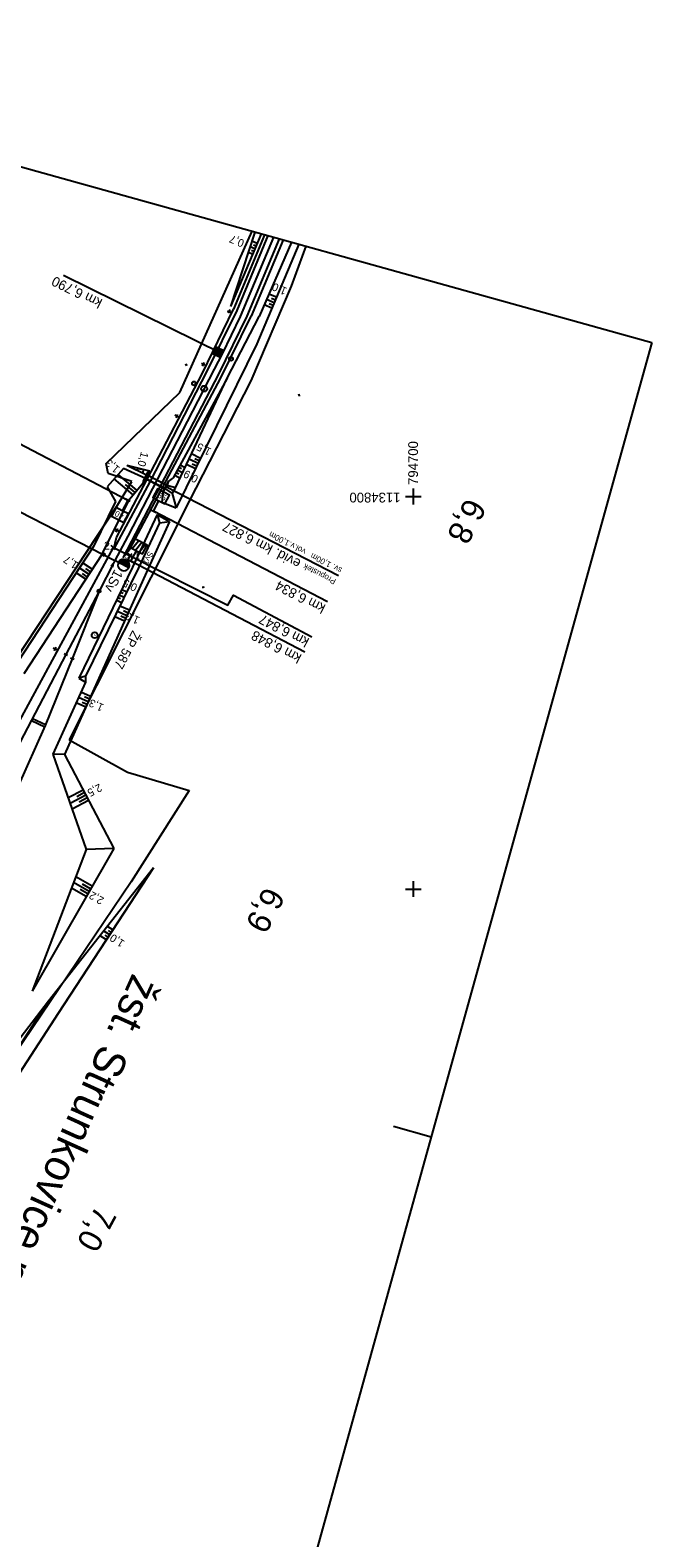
# Model space of a CAD drawing. Extents: x -795094 to -794639, y -1135368 to -1134681.
# Drawn here: x -794797.7 to -794639.2, y -1135065.2 to -1134681.2 of the extents above; entities that cross this region are included whole.
import ezdxf

# ---------------------------------------------------------------- set-up
doc = ezdxf.new("R2010")
doc.units = 0
for name, color, linetype in [('0381KM005-009P - Vrstva 1', 7, 'Continuous'), ('0381KM005-009P - Vrstva 19', 7, 'Continuous'), ('0381KM005-009P - Vrstva 2', 7, 'Continuous'), ('0381KM005-009P - Vrstva 23', 7, 'Continuous'), ('0381KM005-009P - Vrstva 28', 7, 'Continuous'), ('0381KM005-009P - Vrstva 3', 7, 'Continuous'), ('0381KM005-009P - Vrstva 33', 7, 'Continuous'), ('0381KM005-009P - Vrstva 4', 7, 'Continuous'), ('0381KM005-009P - Vrstva 48', 7, 'Continuous'), ('0381KM005-009P - Vrstva 49', 7, 'Continuous'), ('0381KM005-009P - Vrstva 5', 7, 'Continuous'), ('0381KM005-009P - Vrstva 51', 7, 'Continuous'), ('0381KM005-009P - Vrstva 6', 7, 'Continuous'), ('0381KM005-009P - Vrstva 7', 7, 'Continuous'), ('Default', 7, 'Continuous'), ('formát', 7, 'Continuous'), ('hran DP - hran DP', 7, 'Continuous'), ('krizky_1000 - souradnice', 7, 'Continuous'), ('krizky_1000 - Vrstva 1', 7, 'Continuous'), ('PSR_C2_1_Lomove_body_Strunkovice - Vrstva 60', 7, 'Continuous'), ('PSR_C2_1_trasa_Strunkovice - Kabelová trasa', 7, 'Continuous'), ('vyt_sit - stávající', 7, 'Continuous')]:
    doc.layers.add(name, color=color, linetype=linetype)

msp = doc.modelspace()

# ---------------------------------------------------------------- linework, layer by layer
at = {"layer": '0381KM005-009P - Vrstva 1'}
for points in [[(-794735.66, -1134733.94), (-794744.1, -1134754.13), (-794748.76, -1134763.69), (-794750.73, -1134767.6), (-794757.62, -1134780.92)], [(-794757.62, -1134780.92), (-794772.8, -1134810.07), (-794776.07, -1134816.32)], [(-794776.07, -1134816.32), (-794776.43, -1134817.02), (-794780.11, -1134824.07), (-794788.58, -1134840.28)], [(-794776.07, -1134816.32), (-794776.43, -1134817.02), (-794780.11, -1134824.07), (-794786.96, -1134841.36)], [(-794788.58, -1134840.28), (-794803.19, -1134868.16), (-794810.38, -1134881.86), (-794818.66, -1134897.6), (-794826.62, -1134912.5), (-794834.33, -1134926.85), (-794861.92, -1134977.99)], [(-794786.96, -1134841.36), (-794793.84, -1134858.32), (-794800.91, -1134874.12), (-794807.73, -1134887.87), (-794826.52, -1134924.29), (-794833.34, -1134937.13), (-794839.37, -1134947.86), (-794840.75, -1134950.16), (-794846.08, -1134958.61), (-794850.88, -1134965.55), (-794860.1, -1134978.74)]]:
    msp.add_lwpolyline(points, dxfattribs=at)
at = {"layer": '0381KM005-009P - Vrstva 19'}
for p, q in [((-794767.26, -1134793.5), (-794768.87, -1134796.52)), ((-794768.87, -1134796.52), (-794768.27, -1134795.41)), ((-794768.27, -1134795.41), (-794767.82, -1134794.57)), ((-794768.27, -1134795.41), (-794768.27, -1134795.41)), ((-794763.3, -1134797.99), (-794768.27, -1134795.41)), ((-794768.27, -1134795.41), (-794763.33, -1134798.06)), ((-794767.82, -1134794.57), (-794767.26, -1134793.5)), ((-794767.82, -1134794.57), (-794767.82, -1134794.57)), ((-794762.85, -1134797.19), (-794767.82, -1134794.57)), ((-794762.89, -1134797.15), (-794767.82, -1134794.57)), ((-794763.85, -1134798.98), (-794762.37, -1134796.11)), ((-794762.89, -1134797.15), (-794763.33, -1134798.06)), ((-794762.85, -1134797.19), (-794762.89, -1134797.15)), ((-794762.37, -1134796.11), (-794762.85, -1134797.19)), ((-794763.3, -1134797.99), (-794763.85, -1134798.98)), ((-794763.33, -1134798.06), (-794763.3, -1134797.99)), ((-794719.1, -1134820.2), (-794763.06, -1134797.51))]:
    msp.add_line(p, q, dxfattribs=at)
at = {"layer": '0381KM005-009P - Vrstva 2'}
for p, q in [((-794815.95, -1134795.81), (-794776.07, -1134816.32)), ((-794775.14, -1134816.79), (-794776.07, -1134816.32)), ((-794774.93, -1134816.49), (-794774.77, -1134816.98)), ((-794774.61, -1134816.22), (-794774.29, -1134817.23)), ((-794774.26, -1134816.06), (-794773.81, -1134817.48)), ((-794773.89, -1134816), (-794773.33, -1134817.72)), ((-794773.47, -1134816.05), (-794772.86, -1134817.97)), ((-794773, -1134816.26), (-794772.46, -1134817.95)), ((-794772.54, -1134818.13), (-794775.14, -1134816.79)), ((-794772.54, -1134818.13), (-794772.54, -1134818.13)), ((-794780.11, -1134824.07), (-794786.96, -1134841.36)), ((-794788.14, -1134840.51), (-794789.03, -1134840.05)), ((-794786.49, -1134841.55), (-794787.42, -1134841.18))]:
    msp.add_line(p, q, dxfattribs=at)
for points in [[(-794776.07, -1134816.32), (-794776.43, -1134817.02), (-794780.11, -1134824.07), (-794788.58, -1134840.28)], [(-794776.64, -1134817.99), (-794776.43, -1134817.02), (-794777.1, -1134817.76)]]:
    msp.add_lwpolyline(points, dxfattribs=at)
msp.add_circle((-794780.11, -1134824.07), 0.4, dxfattribs=at)
for start, end in [(332.7997, 152.7606), (152.7102, 333.1797)]:
    msp.add_arc((-794773.84, -1134817.46), 1.46, start, end, dxfattribs=at)
at = {"layer": '0381KM005-009P - Vrstva 28'}
msp.add_line((-794746.44, -1134764.88), (-794746.48, -1134764.97), dxfattribs=at)
msp.add_circle((-794746.46, -1134764.93), 0.5, dxfattribs=at)
at = {"layer": '0381KM005-009P - Vrstva 3'}
for p, q in [((-794748.76, -1134763.69), (-794789.21, -1134743.71)), ((-794750.35, -1134762.39), (-794749.67, -1134764.36)), ((-794750.12, -1134761.92), (-794749.2, -1134764.59)), ((-794749.64, -1134762.15), (-794748.96, -1134764.11)), ((-794749.16, -1134762.38), (-794748.73, -1134763.64)), ((-794748.69, -1134762.61), (-794748.5, -1134763.16)), ((-794750.81, -1134763.35), (-794750.63, -1134763.89)), ((-794750.58, -1134762.87), (-794750.15, -1134764.12))]:
    msp.add_line(p, q, dxfattribs=at)
msp.add_lwpolyline([(-794748.32, -1134762.79), (-794749.2, -1134764.59), (-794750.99, -1134763.71), (-794750.12, -1134761.92)], close=True, dxfattribs=at)
at = {"layer": '0381KM005-009P - Vrstva 33'}
msp.add_line((-794768.83, -1134796.2), (-794767.55, -1134793.7), dxfattribs=at)
at = {"layer": '0381KM005-009P - Vrstva 4'}
for points in [[(-794737.95, -1134733.31), (-794745.79, -1134752.29)], [(-794737.06, -1134733.55), (-794744.97, -1134752.65)], [(-794734.21, -1134734.35), (-794742.45, -1134754.09)], [(-794733.14, -1134734.64), (-794741.33, -1134754.03)], [(-794744.97, -1134752.65), (-794752.57, -1134767.89), (-794767.17, -1134796.25), (-794776.32, -1134813.35), (-794775.69, -1134810.46), (-794767.89, -1134795.76), (-794753.75, -1134768.59), (-794745.79, -1134752.29)], [(-794742.45, -1134754.09), (-794749.67, -1134768.83), (-794764.43, -1134797.23), (-794773.98, -1134815.47), (-794772.27, -1134813.39), (-794763.8, -1134797.42), (-794749.03, -1134769.75), (-794741.33, -1134754.03)]]:
    msp.add_lwpolyline(points, dxfattribs=at)
at = {"layer": '0381KM005-009P - Vrstva 48'}
for p, q in [((-794739.8, -1134735.54), (-794741.14, -1134734.97)), ((-794740.97, -1134738.3), (-794742.08, -1134737.83)), ((-794740.39, -1134736.92), (-794741.61, -1134736.4)), ((-794740.68, -1134737.61), (-794741.26, -1134737.36)), ((-794740.09, -1134736.23), (-794740.73, -1134735.96)), ((-794736.03, -1134752.03), (-794738.01, -1134751.2)), ((-794735.45, -1134750.65), (-794737.41, -1134749.82)), ((-794734.87, -1134749.26), (-794736.81, -1134748.45)), ((-794735.74, -1134751.34), (-794736.72, -1134750.92)), ((-794735.16, -1134749.96), (-794736.13, -1134749.54)), ((-794754.22, -1134790.28), (-794756.53, -1134789.14)), ((-794770.26, -1134792.73), (-794770.4, -1134793.3)), ((-794769.53, -1134792.91), (-794769.62, -1134793.27)), ((-794768.8, -1134793.1), (-794769.03, -1134793.97)), ((-794760.11, -1134793.21), (-794758.79, -1134793.93)), ((-794759.75, -1134792.55), (-794759.11, -1134792.9)), ((-794759.39, -1134791.89), (-794758.15, -1134792.57)), ((-794755.55, -1134792.97), (-794757.81, -1134791.86)), ((-794754.88, -1134791.63), (-794757.17, -1134790.5)), ((-794755.21, -1134792.3), (-794756.35, -1134791.74)), ((-794754.55, -1134790.95), (-794755.7, -1134790.39)), ((-794771.4, -1134799.56), (-794776.25, -1134795.52)), ((-794770.44, -1134798.41), (-794775.25, -1134794.4)), ((-794770.92, -1134798.98), (-794773.33, -1134796.97)), ((-794760.82, -1134794.53), (-794759.43, -1134795.29)), ((-794760.46, -1134793.87), (-794759.79, -1134794.24)), ((-794783.51, -1134821.05), (-794785.98, -1134819.43)), ((-794782.69, -1134819.79), (-794785.16, -1134818.18)), ((-794783.1, -1134820.42), (-794784.34, -1134819.61)), ((-794781.87, -1134818.54), (-794784.33, -1134816.93)), ((-794782.28, -1134819.17), (-794783.51, -1134818.36)), ((-794774.33, -1134823.66), (-794773.01, -1134824.29)), ((-794775.63, -1134826.36), (-794774.33, -1134826.99)), ((-794775.3, -1134825.69), (-794774.65, -1134826)), ((-794774.98, -1134825.01), (-794773.67, -1134825.64)), ((-794772.39, -1134828.99), (-794774.79, -1134827.92)), ((-794774.65, -1134824.34), (-794774, -1134824.65)), ((-794773.62, -1134831.73), (-794776.11, -1134830.61)), ((-794773.01, -1134830.36), (-794775.45, -1134829.27)), ((-794773.32, -1134831.05), (-794774.55, -1134830.49)), ((-794772.7, -1134829.68), (-794773.91, -1134829.14)), ((-794782.26, -1134850.93), (-794784.73, -1134849.82)), ((-794782.56, -1134851.61), (-794783.8, -1134851.06)), ((-794783.49, -1134853.67), (-794785.97, -1134852.55)), ((-794782.87, -1134852.3), (-794785.35, -1134851.19)), ((-794783.18, -1134852.98), (-794784.42, -1134852.43)), ((-794784.18, -1134874.77), (-794788, -1134876.78)), ((-794783.48, -1134876.09), (-794787.5, -1134878.21)), ((-794782.78, -1134877.42), (-794787, -1134879.64)), ((-794783.83, -1134875.43), (-794785.79, -1134876.46)), ((-794783.13, -1134876.76), (-794785.19, -1134877.84)), ((-794781.89, -1134899.28), (-794786.07, -1134896.89)), ((-794783.38, -1134901.88), (-794787.15, -1134899.73)), ((-794782.63, -1134900.58), (-794786.61, -1134898.31)), ((-794783, -1134901.23), (-794784.94, -1134900.12)), ((-794782.26, -1134899.93), (-794784.3, -1134898.76)), ((-794778.21, -1134912.91), (-794779.82, -1134911.86)), ((-794777.39, -1134911.65), (-794778.88, -1134910.67)), ((-794777.8, -1134912.28), (-794778.58, -1134911.77)), ((-794776.57, -1134910.4), (-794777.95, -1134909.49)), ((-794776.98, -1134911.03), (-794777.7, -1134910.55))]:
    msp.add_line(p, q, dxfattribs=at)
at = {"layer": '0381KM005-009P - Vrstva 49'}
for p, q in [((-794740.37, -1134732.63), (-794746.6, -1134751.57)), ((-794738.76, -1134733.08), (-794746.6, -1134751.57)), ((-794729.18, -1134735.74), (-794739.85, -1134761.11)), ((-794731.07, -1134735.22), (-794739.3, -1134754.18)), ((-794747.45, -1134769.82), (-794739.3, -1134754.18)), ((-794739.85, -1134761.11), (-794760.44, -1134802.9)), ((-794757.66, -1134766.37), (-794758.14, -1134766.52)), ((-794757.97, -1134766.21), (-794757.82, -1134766.69)), ((-794747.45, -1134769.82), (-794761.22, -1134795.28)), ((-794760.61, -1134797.81), (-794747.45, -1134769.82)), ((-794728.89, -1134774.12), (-794729.36, -1134774.28)), ((-794729.21, -1134773.96), (-794729.05, -1134774.44)), ((-794773.87, -1134792.87), (-794778.08, -1134797.54)), ((-794768.27, -1134795.41), (-794773.87, -1134792.87)), ((-794773.02, -1134792.01), (-794767.82, -1134794.57)), ((-794773.02, -1134792.01), (-794767.26, -1134793.5)), ((-794772.33, -1134800.68), (-794768.87, -1134796.52)), ((-794768.27, -1134795.41), (-794768.87, -1134796.52)), ((-794767.82, -1134794.57), (-794767.26, -1134793.5)), ((-794762.37, -1134796.11), (-794763.85, -1134798.98)), ((-794762.85, -1134797.19), (-794762.37, -1134796.11)), ((-794760.61, -1134797.81), (-794762.85, -1134797.19)), ((-794761.22, -1134795.28), (-794762.37, -1134796.11)), ((-794779.34, -1134814.68), (-794772.33, -1134800.68)), ((-794778.08, -1134797.54), (-794775.92, -1134801.3)), ((-794763.85, -1134798.98), (-794764.14, -1134801.43)), ((-794763.3, -1134797.99), (-794763.85, -1134798.98)), ((-794763.3, -1134797.99), (-794761.44, -1134799.24)), ((-794761.44, -1134799.24), (-794760.61, -1134797.81)), ((-794761.44, -1134799.24), (-794760.44, -1134802.9)), ((-794775.92, -1134801.3), (-794781.56, -1134812.71)), ((-794765.33, -1134804.62), (-794771.57, -1134817.97)), ((-794765.33, -1134804.62), (-794764.66, -1134806.73)), ((-794765.33, -1134804.62), (-794762.15, -1134806.37)), ((-794764.14, -1134801.43), (-794760.44, -1134802.9)), ((-794764.66, -1134806.73), (-794770.02, -1134818.19)), ((-794762.15, -1134806.37), (-794768.04, -1134819.3)), ((-794764.66, -1134806.73), (-794762.15, -1134806.37)), ((-794781.56, -1134812.71), (-794806.26, -1134850.22)), ((-794779.34, -1134814.68), (-794799.26, -1134845.15)), ((-794768.04, -1134819.3), (-794788.91, -1134865.74)), ((-794771.57, -1134817.97), (-794785.26, -1134846.3)), ((-794770.02, -1134818.19), (-794783.54, -1134845.78)), ((-794753.32, -1134823.06), (-794753.8, -1134823.21)), ((-794753.64, -1134822.9), (-794753.49, -1134823.38)), ((-794783.54, -1134845.78), (-794785.26, -1134846.3)), ((-794785.26, -1134846.3), (-794783.58, -1134847.29)), ((-794783.54, -1134845.78), (-794783.58, -1134847.29)), ((-794783.58, -1134847.29), (-794791.9, -1134865.62)), ((-794791.9, -1134865.62), (-794783.41, -1134889.91)), ((-794788.91, -1134865.74), (-794791.9, -1134865.62)), ((-794788.91, -1134865.74), (-794776.38, -1134889.62)), ((-794776.38, -1134889.62), (-794797.15, -1134926.02)), ((-794783.41, -1134889.91), (-794797.15, -1134926.02)), ((-794776.38, -1134889.62), (-794783.41, -1134889.91)), ((-794766.19, -1134894.56), (-794792.99, -1134928.57)), ((-794766.19, -1134894.56), (-794790.5, -1134931.65)), ((-794790.5, -1134931.65), (-794824.29, -1134983.58)), ((-794792.99, -1134928.57), (-794819.56, -1134969.3)), ((-794792.99, -1134928.57), (-794819.08, -1134962.42))]:
    msp.add_line(p, q, dxfattribs=at)
at = {"layer": '0381KM005-009P - Vrstva 5'}
for p, q in [((-794808.79, -1134782.22), (-794772.81, -1134800.95)), ((-794772.14, -1134801.3), (-794773.47, -1134800.61)), ((-794766.9, -1134803.37), (-794765.57, -1134804.07)), ((-794721.88, -1134826.8), (-794766.23, -1134803.72))]:
    msp.add_line(p, q, dxfattribs=at)
for points in [[(-794772.81, -1134800.95), (-794774.19, -1134803.61), (-794775.74, -1134802.81), (-794776.9, -1134805.02), (-794773.79, -1134806.64), (-794772.64, -1134804.42), (-794774.19, -1134803.61)], [(-794766.23, -1134803.72), (-794764.85, -1134801.06), (-794763.3, -1134801.87), (-794762.14, -1134799.65), (-794765.25, -1134798.03), (-794766.4, -1134800.25), (-794764.85, -1134801.06)]]:
    msp.add_lwpolyline(points, dxfattribs=at)
at = {"layer": '0381KM005-009P - Vrstva 51'}
msp.add_lwpolyline([(-794871.74, -1135021.34), (-794845.86, -1135006.13), (-794837.37, -1134998.39), (-794824.29, -1134983.58), (-794790.5, -1134931.65), (-794766.19, -1134894.56)], dxfattribs=at)
at = {"layer": '0381KM005-009P - Vrstva 6'}
for p, q in [((-794773.1, -1134816.84), (-794772.18, -1134815.08)), ((-794771.74, -1134815.31), (-794772.62, -1134814.85))]:
    msp.add_line(p, q, dxfattribs=at)
msp.add_lwpolyline([(-794772.18, -1134815.08), (-794747.28, -1134827.67), (-794745.87, -1134825.09), (-794725.88, -1134835.7)], dxfattribs=at)
at = {"layer": '0381KM005-009P - Vrstva 7'}
for p, q in [((-794747.36, -1134752.67), (-794746.44, -1134753.06)), ((-794747.09, -1134753.33), (-794746.71, -1134752.4)), ((-794753.12, -1134766.56), (-794754.01, -1134766.1)), ((-794753.33, -1134765.88), (-794753.79, -1134766.77)), ((-794755.87, -1134771.14), (-794755.92, -1134771.23)), ((-794759.86, -1134779.78), (-794760.75, -1134779.32)), ((-794760.07, -1134779.1), (-794760.53, -1134779.99)), ((-794775.17, -1134808.86), (-794776.06, -1134808.4)), ((-794775.38, -1134808.18), (-794775.84, -1134809.07)), ((-794771.69, -1134813.25), (-794770.09, -1134811.26)), ((-794769.2, -1134811.73), (-794770.8, -1134813.71)), ((-794769.92, -1134814.17), (-794768.32, -1134812.19)), ((-794778.43, -1134815.06), (-794779.32, -1134814.6)), ((-794778.65, -1134814.39), (-794779.11, -1134815.27)), ((-794772.64, -1134816.14), (-794771.31, -1134816.83)), ((-794727.67, -1134839.67), (-794771.97, -1134816.49)), ((-794790.89, -1134839.08), (-794791.78, -1134838.62)), ((-794791.11, -1134838.41), (-794791.57, -1134839.3)), ((-794797.37, -1134857.06), (-794793.96, -1134858.64)), ((-794797.09, -1134856.53), (-794793.74, -1134858.08))]:
    msp.add_line(p, q, dxfattribs=at)
msp.add_lwpolyline([(-794771.97, -1134816.49), (-794770.58, -1134813.83), (-794769.03, -1134814.64), (-794767.87, -1134812.42), (-794770.97, -1134810.8), (-794772.13, -1134813.02), (-794770.58, -1134813.83)], dxfattribs=at)
for centre, radius in [((-794755.9, -1134771.19), 0.5), ((-794753.29, -1134772.54), 0.75)]:
    msp.add_circle(centre, radius, dxfattribs=at)
at = {"layer": 'formát'}
for p, q in [((-794925.31, -1134681.22), (-794639.16, -1134760.77)), ((-794639.16, -1134760.77), (-794695.41, -1134963.1)), ((-794705.05, -1134960.42), (-794695.41, -1134963.1)), ((-794705.05, -1134960.42), (-794695.41, -1134963.1)), ((-794695.41, -1134963.1), (-794751.67, -1135165.42))]:
    msp.add_line(p, q, dxfattribs=at)
at = {"layer": 'hran DP - hran DP'}
for p, q in [((-794759.53, -1134773.54), (-794741.05, -1134732.44)), ((-794727.43, -1134736.23), (-794731.15, -1134746.39)), ((-794731.15, -1134746.39), (-794741.45, -1134770.5)), ((-794778.33, -1134791.56), (-794759.53, -1134773.54)), ((-794741.45, -1134770.5), (-794758.9, -1134804.63)), ((-794777.82, -1134794.18), (-794778.33, -1134791.56)), ((-794771.78, -1134796.16), (-794777.82, -1134794.18)), ((-794775.44, -1134802.2), (-794771.78, -1134796.16)), ((-794808.02, -1134851.51), (-794775.44, -1134802.2)), ((-794758.9, -1134804.63), (-794759.9, -1134806.76)), ((-794759.9, -1134806.76), (-794787.72, -1134861.99)), ((-794787.72, -1134861.99), (-794772.84, -1134870.22)), ((-794772.84, -1134870.22), (-794757.13, -1134874.85)), ((-794757.13, -1134874.85), (-794771.93, -1134898.11)), ((-794771.93, -1134898.11), (-794808.62, -1134952.39))]:
    msp.add_line(p, q, dxfattribs=at)
at = {"layer": 'krizky_1000 - Vrstva 1'}
for points in [[(-794702, -1134800), (-794698, -1134800)], [(-794700, -1134798), (-794700, -1134802)], [(-794702, -1134900), (-794698, -1134900)], [(-794700, -1134898), (-794700, -1134902)]]:
    msp.add_lwpolyline(points, dxfattribs=at)
at = {"layer": 'PSR_C2_1_Lomove_body_Strunkovice - Vrstva 60'}
for p, q in [((-794776.99, -1134813.55), (-794775.89, -1134812.45)), ((-794775.89, -1134813.55), (-794776.99, -1134812.45)), ((-794772.73, -1134815.63), (-794771.63, -1134814.53)), ((-794771.63, -1134815.63), (-794772.73, -1134814.53))]:
    msp.add_line(p, q, dxfattribs=at)
at = {"layer": 'PSR_C2_1_trasa_Strunkovice - Kabelová trasa'}
msp.add_lwpolyline([(-794859.57, -1134988.66), (-794835.3, -1134945.55), (-794845.51, -1134940.37), (-794776.44, -1134813), (-794772.18, -1134815.08)], dxfattribs=at)
at = {"layer": 'vyt_sit - stávající'}
msp.add_line((-794781.21, -1134835.29), (-794781.25, -1134835.37), dxfattribs=at)
msp.add_circle((-794781.23, -1134835.33), 0.756, dxfattribs=at)

# ---------------------------------------------------------------- texts
at = {"layer": '0381KM005-009P - Vrstva 19'}
for s, height, p in [('evid. km 6,827', 2.5, (-794728.46, -1134816.29)), ('sv. 1,00m   vol.v.1,00m', 1.5, (-794717.99, -1134818.3)), ('Propustek', 1.5, (-794719.55, -1134821.16))]:
    msp.add_text(s, height=height, rotation=152.7057, dxfattribs=at).set_placement(p)
at = {"layer": '0381KM005-009P - Vrstva 2'}
msp.add_text('1Sv', height=2.5, rotation=242.4084, dxfattribs=at).set_placement((-794776.11, -1134818.38))
at = {"layer": '0381KM005-009P - Vrstva 23'}
msp.add_text('žst. Strunkovice nad Volyňkou', height=8, rotation=245.663, dxfattribs=at).set_placement((-794771.54, -1134921.22))
at = {"layer": '0381KM005-009P - Vrstva 3'}
msp.add_text('km 6,790', height=2.5, rotation=153.7108, dxfattribs=at).set_placement((-794779.06, -1134749.9))
at = {"layer": '0381KM005-009P - Vrstva 48'}
for s, rotation, p in [('0,7', 157.0225, (-794742.9, -1134734.77)), ('1,0', 157.1828, (-794732.04, -1134746.95)), ('1,0', 255.4428, (-794769.39, -1134788.47)), ('1,5', 153.7759, (-794751.28, -1134787.9)), ('1,3', 140.2012, (-794774.66, -1134792.71)), ('0,9', 151.5692, (-794754.62, -1134794.92)), ('1,7', 146.832, (-794785.24, -1134816.96)), ('0,5', 154.2119, (-794770.15, -1134822.51)), ('1,3', 155.7895, (-794769.58, -1134830.83)), ('1,3', 155.7895, (-794778.72, -1134853.04)), ('2,5', 207.6821, (-794780.03, -1134873.07)), ('2,2', 150.2833, (-794778.67, -1134902.33)), ('1,0', 146.755, (-794773.41, -1134913.32))]:
    msp.add_text(s, height=2, rotation=rotation, dxfattribs=at).set_placement(p)
at = {"layer": '0381KM005-009P - Vrstva 5'}
for s, height, rotation, p in [('55', 1.5, 332.5023, (-794765.41, -1134800.15)), ('40', 1.5, 152.5023, (-794773.63, -1134804.52)), ('km 6,834', 2.5, 152.5023, (-794722.13, -1134827.68))]:
    msp.add_text(s, height=height, rotation=rotation, dxfattribs=at).set_placement(p)
at = {"layer": '0381KM005-009P - Vrstva 6'}
for s, height, rotation, p in [('  A ', 1, 242.3746, (-794773.07, -1134814.62)), ('Sv1', 1.5, 242.5023, (-794767.44, -1134813.81)), ('km 6,847', 2.5, 152.3746, (-794726.31, -1134836.27))]:
    msp.add_text(s, height=height, rotation=rotation, dxfattribs=at).set_placement(p)
at = {"layer": '0381KM005-009P - Vrstva 7'}
for s, height, rotation, p in [('6,8', 6, 242.6352, (-794686.43, -1134800.02)), ('km 6,848', 2.5, 152.3746, (-794728.26, -1134840.39)), ('6,9', 6, 242.3222, (-794737.76, -1134899.06)), ('7,0', 6, 241.6619, (-794780.73, -1134980.29))]:
    msp.add_text(s, height=height, rotation=rotation, dxfattribs=at).set_placement(p)
at = {"layer": 'Default'}
for s, p in [('2', (-794778.83, -1134813.5)), ('1', (-794771.19, -1134815.98))]:
    msp.add_text(s, height=2, dxfattribs=at).set_placement(p)
at = {"layer": 'krizky_1000 - souradnice'}
for s, rotation, p in [('794700', 90, (-794698.79, -1134797.05)), ('1134800', 180, (-794703.26, -1134799.02))]:
    msp.add_text(s, height=2.5, rotation=rotation, dxfattribs=at).set_placement(p)
at = {"layer": 'vyt_sit - stávající'}
msp.add_text('ŽP 587', height=2.4, rotation=242.405, dxfattribs=at).set_placement((-794771.57, -1134833.95))

doc.saveas('drawing.dxf')
